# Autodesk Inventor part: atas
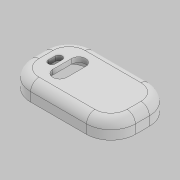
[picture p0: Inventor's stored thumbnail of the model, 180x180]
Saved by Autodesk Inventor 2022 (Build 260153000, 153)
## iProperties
Created: 2022-06
Part Number: atas
Material: Generic
Document SubType Name: Modeling
Designer: Dragon
Density: 1 g/cm^3
Appearance: Default
Author: Dragon
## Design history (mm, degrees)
sketch "Sketch1"
  geometry: L1 (400, -450)-(-400, -450); L2 (-750, -100)-(-750, 100); L3 (-400, 450)-(400, 450); L4 (750, 100)-(750, -100); L5 (750, -450)-(-750, 450); L6 (-750, -450)-(750, 450); A1 r 350 centre (400, -100) between (400, -450) and (750, -100); A2 r 350 centre (-400, -100) between (-750, -100) and (-400, -450); A3 r 350 centre (-400, 100) between (-400, 450) and (-750, 100); A4 r 350 centre (400, 100) between (750, 100) and (400, 450); 1 further point
  constraints: 12 end point, 8 point on circle, 8 point on line, 8 tangent, 4 centre point, 3 equal radius, 2 midpoint, 2 parallel, 1 horizontal, 1 perpendicular
  dimensions: "d0" = 1500 distance of L5.end L6.end; "d1" = 900 distance of L6.start L5.end; "d2" = 350 radius of A1
extrude "Extrusion1" new body sketch "Sketch1" distance "d3" = 250; taper "d4" = 0 deg
fillet "Fillet1" dims "d5" = 120
shell "Shell1" dims "d6" = 70
sketch "Sketch4"
  geometry: L1 (680, 100)-(680, -100) reference; L2 (680, 0)-(710, 0); L3 (400, -380)-(-400, -380) reference; L4 (0, -380)-(0, -410); C1 r 20 at (710, 0); C2 r 20 at (0, -410); 1 further point
  constraints: 4 end point, 2 centre point, 2 coincident, 2 midpoint, 1 horizontal, 1 vertical
  dimensions: "d21" = 30 distance of L2.start L2.end; "d22" = 30 distance of L4.start L4.end; "d23" = 40 diameter of C1; "d24" = 40 diameter of C2
extrude "Extrusion4" cut sketch "Sketch4" distance "d25" = 30; taper "d26" = 0 deg
mirror "Mirror1"
mirror "Mirror2"
sketch "Sketch6"
  geometry: L1 (-297.266, -135)-(-297.266, 135); L2 (-197.266, -135)-(-197.266, 135); L3 (-397.266, 135)-(-397.266, -135); L4 (-497.178, -50)-(-497.178, 50); L5 (-447.178, -50)-(-447.178, 50); L6 (-547.178, 50)-(-547.178, -50); C1 r 100 at (-297.266, 135); C2 r 100 at (-297.266, -135); A1 r 100 centre (-297.266, -135) between (-397.266, -135) and (-197.266, -135); A2 r 100 centre (-297.266, 135) between (-197.266, 135) and (-397.266, 135); A3 r 50 centre (-497.178, -50) between (-547.178, -50) and (-447.178, -50); A4 r 50 centre (-497.178, 50) between (-447.178, 50) and (-547.178, 50); 11 further points
  constraints: 16 end point, 8 point on circle, 8 tangent, 6 centre point, 3 parallel, 2 coincident, 2 concentric, 2 midpoint, 1 vertical
  dimensions: "d31" = 270 distance of L1.start L1.end; "d32" = 200 diameter of A2; "d36" = 50 distance of point (-497.178, 0) L4.end; "d37" = 100 diameter of A4
extrude "Extrusion6" cut sketch "Sketch6" distance "d34" = 250; taper "d35" = 0 deg
body "Solid1"
